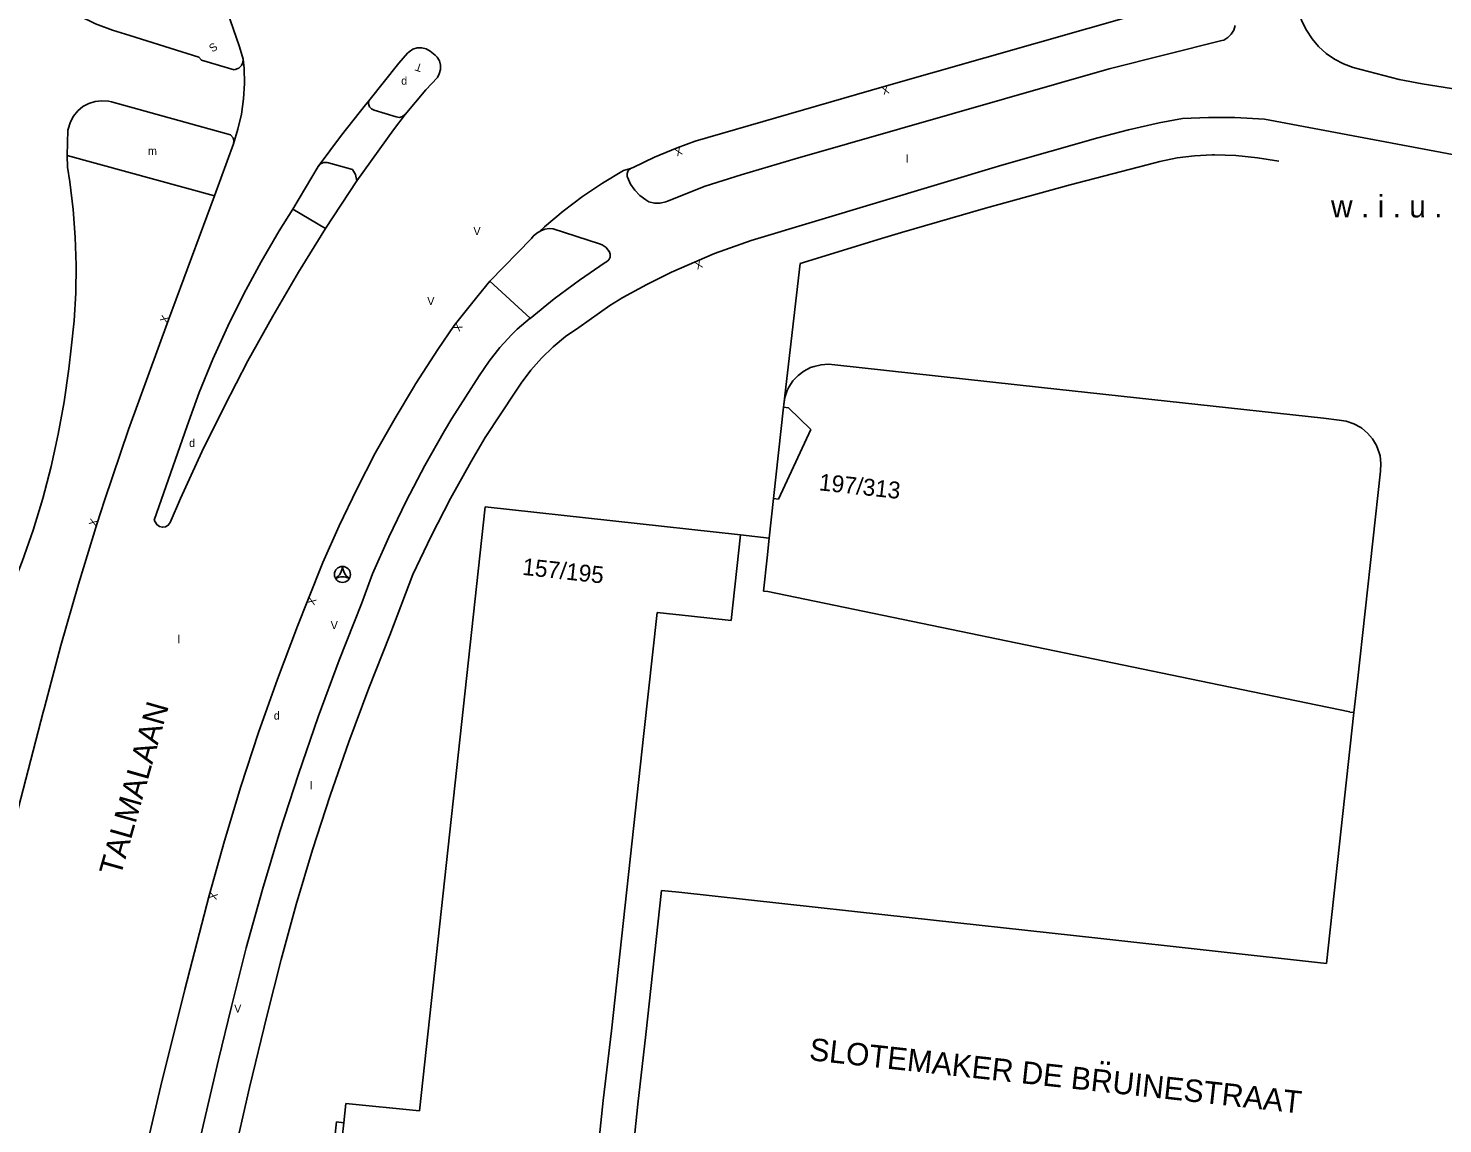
# Model space of a CAD drawing. Extents: x 134999 to 136502, y 457398 to 459002.
# Drawn here: x 136333.3 to 136421.7, y 457501.4 to 457569.8 of the extents above; entities that cross this region are included whole.
import ezdxf

# ---------------------------------------------------------------- set-up
doc = ezdxf.new("R2010")
doc.units = 0
for name, color, linetype in [('RI_DGTB_2', 7, 'Continuous'), ('RI_DGTB_29', 7, 'Continuous'), ('RI_DGTB_30', 7, 'Continuous'), ('RI_DGTB_31', 7, 'Continuous'), ('RI_DGTB_35', 7, 'Continuous'), ('RI_DGTB_37', 7, 'Continuous'), ('RI_DGTB_41', 7, 'Continuous'), ('RI_DGTB_43', 7, 'Continuous'), ('RI_DGTB_53', 7, 'Continuous')]:
    doc.layers.add(name, color=color, linetype=linetype)

msp = doc.modelspace()

# ---------------------------------------------------------------- linework, layer by layer
at = {"layer": 'RI_DGTB_2'}
for p, q in [((136383.707, 457548.805), (136396.602, 457547.404)), ((136396.602, 457547.404), (136414.227, 457545.473)), ((136380.802, 457546.12), (136380.484, 457546.155)), ((136380.802, 457546.12), (136382.208, 457544.769)), ((136382.208, 457544.769), (136380.185, 457540.413)), ((136415.208, 457545.362), (136414.227, 457545.473)), ((136416.337, 457529.049), (136417.785, 457542.17)), ((136380.185, 457540.413), (136379.867, 457540.448)), ((136357.748, 457502.191), (136361.858, 457539.928)), ((136361.858, 457539.928), (136377.797, 457538.177)), ((136377.797, 457538.177), (136377.215, 457532.834)), ((136377.797, 457538.177), (136379.6, 457537.982)), ((136379.238, 457534.668), (136379.467, 457536.757)), ((136379.238, 457534.668), (136379.519, 457534.648)), ((136406.472, 457529.066), (136379.519, 457534.648)), ((136406.472, 457529.066), (136415.875, 457527.123)), ((136416.337, 457529.049), (136416.12, 457527.078)), ((136416.12, 457527.078), (136414.41, 457511.403)), ((136415.873, 457527.098), (136415.875, 457527.123)), ((136416.12, 457527.078), (136415.873, 457527.098)), ((136372.873, 457515.963), (136371.882, 457506.957)), ((136372.873, 457515.963), (136373.958, 457515.852)), ((136373.958, 457515.852), (136386.818, 457514.44)), ((136386.818, 457514.44), (136400.116, 457512.982)), ((136400.116, 457512.982), (136414.41, 457511.403)), ((136369.743, 457507.19), (136369.234, 457502.841)), ((136371.882, 457506.957), (136371.396, 457502.605)), ((136353.154, 457502.648), (136357.748, 457502.191)), ((136369.234, 457502.841), (136368.971, 457500.431)), ((136371.396, 457502.605), (136371.133, 457500.195)), ((136352.264, 457498.731), (136352.569, 457501.494))]:
    msp.add_line(p, q, dxfattribs=at)
for points in [[(136380.823, 457547.412), (136381.079, 457547.801), (136381.398, 457548.142), (136381.771, 457548.423), (136382.186, 457548.636), (136382.397, 457548.713)], [(136382.397, 457548.713), (136382.843, 457548.82), (136383.3, 457548.848), (136383.707, 457548.805)], [(136380.503, 457546.331), (136380.57, 457546.774), (136380.715, 457547.198), (136380.823, 457547.412)], [(136379.867, 457540.448), (136380.484, 457546.155)], [(136380.484, 457546.155), (136380.503, 457546.331)], [(136416.547, 457544.899), (136416.11, 457545.129), (136415.642, 457545.287), (136415.208, 457545.362)], [(136417.707, 457543.318), (136417.534, 457543.765), (136417.289, 457544.177), (136416.979, 457544.543), (136416.613, 457544.853), (136416.547, 457544.899)], [(136417.785, 457542.17), (136417.809, 457542.648), (136417.753, 457543.123), (136417.707, 457543.318)], [(136379.6, 457537.982), (136379.867, 457540.448)], [(136379.467, 457536.757), (136379.6, 457537.982)], [(136372.591, 457533.331), (136371.768, 457525.777)], [(136374.74, 457533.1), (136372.591, 457533.331)], [(136377.215, 457532.834), (136374.74, 457533.1)], [(136371.768, 457525.777), (136369.743, 457507.19)], [(136353.154, 457502.648), (136353.02, 457501.444)], [(136352.569, 457501.494), (136353.02, 457501.444)], [(136353.02, 457501.444), (136352.712, 457498.682)]]:
    msp.add_lwpolyline(points, dxfattribs=at)
at = {"layer": 'RI_DGTB_31'}
msp.add_circle((136352.941, 457535.713), 0.5, dxfattribs=at)
for centre, radius, start, end in [((136351.959, 457536.281), 0.984, 303.89611, 356.03804), ((136353.921, 457536.28), 0.982, 183.93068, 236.24524), ((136352.941, 457534.564), 0.999, 64.2764, 115.72044)]:
    msp.add_arc(centre, radius, start, end, dxfattribs=at)
at = {"layer": 'RI_DGTB_53'}
for p, q in [((136346.176, 457567.241), (136344.128, 457567.847)), ((136358.739, 457568.158), (136358.412, 457568.405)), ((136418.951, 457566.64), (136416.07, 457567.389)), ((136338.519, 457565.242), (136345.951, 457563.175)), ((136354.926, 457564.722), (136356.306, 457564.301)), ((136335.736, 457561.886), (136344.944, 457559.364)), ((136352.063, 457561.444), (136353.577, 457561.009)), ((136349.841, 457558.531), (136351.426, 457561.215)), ((136370.49, 457560.95), (136370.931, 457561.085)), ((136353.838, 457560.312), (136351.883, 457557.325)), ((136373.25, 457559.035), (136375.598, 457559.983)), ((136349.841, 457558.531), (136351.883, 457557.325)), ((136368.989, 457556.383), (136366.112, 457557.3)), ((136378.462, 457556.59), (136376.191, 457555.776)), ((136376.191, 457555.776), (136375.07, 457555.29)), ((136362.149, 457554.038), (136361.959, 457553.803)), ((136364.658, 457551.717), (136362.149, 457554.038)), ((136363.854, 457551.034), (136364.658, 457551.717)), ((136369.64, 457552.524), (136367.703, 457551.153)), ((136341.187, 457539.112), (136343.234, 457545.007)), ((136354.825, 457535.757), (136354.121, 457533.874)), ((136357.337, 457535.707), (136355.906, 457531.912))]:
    msp.add_line(p, q, dxfattribs=at)
for points in [[(136342.899, 457576.881), (136343.766, 457575.308), (136344.562, 457573.699), (136345.286, 457572.055), (136345.936, 457570.381), (136346.51, 457568.68), (136346.74, 457567.921)], [(136373.85, 457562.374), (136374.967, 457562.791), (136386.769, 457566.213), (136402.637, 457570.732), (136407.626, 457572.206)], [(136339.667, 457569.387), (136338.581, 457569.721), (136337.521, 457570.131), (136336.493, 457570.615), (136335.502, 457571.169), (136334.563, 457571.784)], [(136416.07, 457567.389), (136415.474, 457567.613), (136414.912, 457567.909), (136414.391, 457568.274), (136413.92, 457568.702), (136413.506, 457569.185), (136413.156, 457569.716), (136412.875, 457570.287), (136412.668, 457570.889), (136412.538, 457571.512), (136412.527, 457571.599)], [(136344.128, 457567.847), (136343.98, 457568.035), (136339.667, 457569.387)], [(136408.695, 457570.018), (136408.617, 457569.727), (136408.465, 457569.468), (136408.251, 457569.258), (136407.989, 457569.111), (136407.878, 457569.074)], [(136358.412, 457568.405), (136358.168, 457568.552), (136357.893, 457568.626), (136357.609, 457568.621), (136357.337, 457568.538), (136357.098, 457568.382), (136357.007, 457568.292)], [(136407.878, 457569.074), (136400.835, 457567.307), (136381.22, 457561.683)], [(136346.126, 457562.628), (136346.416, 457563.542), (136346.63, 457564.477), (136346.764, 457565.426), (136346.819, 457566.383), (136346.794, 457567.342), (136346.74, 457567.921)], [(136346.74, 457567.921), (136346.722, 457567.705), (136346.628, 457567.509), (136346.471, 457567.361), (136346.176, 457567.241)], [(136357.008, 457568.293), (136356.46, 457567.656), (136354.597, 457565.316)], [(136358.983, 457566.993), (136359.067, 457567.259), (136359.073, 457567.537), (136358.999, 457567.805), (136358.853, 457568.042), (136358.738, 457568.158)], [(136356.854, 457564.464), (136358.149, 457566.002), (136358.884, 457566.759), (136358.984, 457566.994)], [(136430.208, 457565.017), (136426.927, 457565.391), (136423.649, 457565.846), (136420.384, 457566.38), (136418.951, 457566.64)], [(136335.78, 457563.47), (136335.946, 457563.995), (136336.146, 457564.361), (136336.412, 457564.682), (136336.734, 457564.947), (136337.1, 457565.145), (136337.498, 457565.27), (136337.912, 457565.317), (136338.328, 457565.285), (136338.519, 457565.242)], [(136351.426, 457561.215), (136352.876, 457563.165), (136354.39, 457565.066), (136354.597, 457565.316)], [(136354.596, 457565.316), (136354.575, 457565.126), (136354.632, 457564.943), (136354.758, 457564.8), (136354.926, 457564.721)], [(136353.838, 457560.312), (136356.139, 457563.501), (136356.854, 457564.464)], [(136356.306, 457564.3), (136356.501, 457564.274), (136356.69, 457564.327), (136356.843, 457564.451), (136356.854, 457564.464)], [(136400.134, 457562.998), (136402.032, 457563.504), (136403.963, 457563.937), (136405.419, 457564.209)], [(136405.419, 457564.209), (136407.048, 457564.277), (136408.679, 457564.264), (136410.541, 457564.158)], [(136410.541, 457564.158), (136429.479, 457560.599), (136433.194, 457559.97)], [(136335.736, 457561.886), (136335.78, 457563.47)], [(136346.126, 457562.628), (136344.944, 457559.364)], [(136345.951, 457563.175), (136346.107, 457562.99), (136346.156, 457562.811), (136346.126, 457562.628)], [(136373.85, 457562.374), (136372.433, 457561.784), (136371.11, 457561.152)], [(136378.462, 457556.59), (136394.132, 457561.287), (136400.134, 457562.998)], [(136335.756, 457561.168), (136335.736, 457561.886)], [(136351.426, 457561.215), (136351.575, 457561.366), (136351.77, 457561.452), (136351.982, 457561.461), (136352.063, 457561.444)], [(136381.22, 457561.683), (136377.837, 457560.693), (136375.598, 457559.983)], [(136403.687, 457561.442), (136398.391, 457560.065), (136393.115, 457558.612), (136387.862, 457557.081), (136386.622, 457556.708)], [(136407.259, 457561.94), (136406.165, 457561.88), (136405.079, 457561.741), (136404.006, 457561.523), (136403.687, 457561.442)], [(136411.428, 457561.544), (136410.096, 457561.755), (136408.754, 457561.887), (136407.406, 457561.939), (136407.259, 457561.94)], [(136335.987, 457549.843), (136336.173, 457551.571), (136336.279, 457553.305), (136336.305, 457555.043), (136336.251, 457556.78), (136336.118, 457558.513), (136335.904, 457560.238), (136335.756, 457561.168)], [(136353.577, 457561.009), (136353.764, 457560.698), (136353.838, 457560.312)], [(136370.49, 457560.95), (136369.191, 457560.172), (136367.934, 457559.326), (136366.724, 457558.415), (136365.564, 457557.442), (136365.219, 457557.132)], [(136371.11, 457561.152), (136370.931, 457561.085), (136370.795, 457560.951), (136370.725, 457560.774), (136370.733, 457560.583), (136370.749, 457560.533)], [(136370.749, 457560.533), (136370.939, 457560.109), (136371.199, 457559.723), (136371.521, 457559.388), (136371.896, 457559.113), (136372.089, 457559.006)], [(136344.944, 457559.364), (136342.073, 457551.614), (136339.572, 457544.779)], [(136372.089, 457559.006), (136372.438, 457558.924), (136372.797, 457558.92), (136373.148, 457558.997), (136373.25, 457559.035)], [(136343.234, 457545.007), (136343.998, 457547.079), (136344.853, 457549.169), (136345.782, 457551.227), (136346.783, 457553.251), (136347.856, 457555.239), (136348.998, 457557.187), (136349.841, 457558.531)], [(136351.883, 457557.325), (136350.199, 457554.612), (136348.585, 457551.858), (136347.04, 457549.065), (136345.565, 457546.234), (136344.162, 457543.367), (136342.831, 457540.465), (136342.171, 457538.951)], [(136365.34, 457557.182), (136365.076, 457557.047), (136364.858, 457556.847), (136364.753, 457556.696)], [(136366.112, 457557.3), (136365.844, 457557.338), (136365.577, 457557.296), (136365.34, 457557.182)], [(136364.753, 457556.696), (136362.148, 457554.038)], [(136369.588, 457555.924), (136369.406, 457556.147), (136369.171, 457556.311), (136368.989, 457556.383)], [(136386.623, 457556.708), (136381.535, 457555.141), (136380.503, 457546.331)], [(136369.427, 457555.248), (136369.574, 457555.373), (136369.657, 457555.545), (136369.664, 457555.737), (136369.593, 457555.915), (136369.588, 457555.924)], [(136375.069, 457555.289), (136373.494, 457554.601), (136371.952, 457553.841), (136370.448, 457553.009), (136369.639, 457552.524)], [(136364.657, 457551.716), (136366.173, 457552.941), (136367.738, 457554.102), (136369.35, 457555.198), (136369.427, 457555.248)], [(136359.921, 457551.269), (136361.333, 457553.033), (136362.149, 457554.038)], [(136357.373, 457547.392), (136357.528, 457547.65), (136358.897, 457549.773), (136359.921, 457551.269)], [(136361.476, 457548.124), (136362.096, 457549.035), (136362.78, 457549.898), (136363.524, 457550.71), (136363.854, 457551.033)], [(136367.703, 457551.152), (136366.875, 457550.573), (136366.097, 457549.931), (136365.371, 457549.229), (136364.703, 457548.472), (136364.097, 457547.664), (136363.765, 457547.157)], [(136331.358, 457532.688), (136332.189, 457534.593), (136332.941, 457536.519), (136333.618, 457538.473), (136334.219, 457540.451), (136334.743, 457542.451), (136335.189, 457544.471), (136335.557, 457546.505), (136335.846, 457548.553), (136335.987, 457549.843)], [(136350.781, 457534.104), (136351.724, 457536.447), (136352.742, 457538.759), (136353.832, 457541.038), (136354.994, 457543.281), (136356.226, 457545.486), (136357.373, 457547.392)], [(136361.476, 457548.124), (136359.771, 457545.461)], [(136361.856, 457544.269), (136363.765, 457547.157)], [(136339.572, 457544.779), (136338.084, 457540.325), (136337.629, 457538.909)], [(136354.825, 457535.757), (136355.84, 457538.043), (136356.927, 457540.296), (136358.086, 457542.513), (136359.315, 457544.692), (136359.771, 457545.461)], [(136357.337, 457535.707), (136358.477, 457538.095), (136359.689, 457540.448), (136360.971, 457542.763), (136361.855, 457544.269)], [(136337.629, 457538.909), (136336.449, 457535.096), (136335.347, 457531.261), (136334.322, 457527.404), (136334.246, 457527.108)], [(136342.171, 457538.951), (136342.058, 457538.79), (136341.89, 457538.686), (136341.695, 457538.656), (136341.504, 457538.705), (136341.347, 457538.826), (136341.187, 457539.112)], [(136344.624, 457515.653), (136345.574, 457519.068), (136346.601, 457522.461), (136347.705, 457525.829), (136348.884, 457529.172), (136350.138, 457532.487), (136350.781, 457534.104)], [(136346.003, 457508.704), (136346.933, 457512.369), (136347.941, 457516.014), (136349.025, 457519.637), (136350.186, 457523.235), (136351.422, 457526.809), (136352.734, 457530.356), (136354.121, 457533.874)], [(136348.248, 457508.183), (136349.113, 457511.642), (136350.055, 457515.081), (136351.073, 457518.498), (136352.168, 457521.891), (136353.339, 457525.259), (136354.585, 457528.6), (136355.906, 457531.912)], [(136334.246, 457527.108), (136332.548, 457520.509), (136332.22, 457519.27)], [(136340.187, 457497.703), (136341.598, 457503.741), (136343.087, 457509.761), (136344.624, 457515.653)], [(136341.332, 457486.425), (136342.175, 457491.165), (136343.101, 457495.916), (136344.105, 457500.651), (136345.188, 457505.368), (136346.003, 457508.704)], [(136343.364, 457484.908), (136344.189, 457489.615), (136345.093, 457494.308), (136346.076, 457498.986), (136347.136, 457503.646), (136348.248, 457508.183)]]:
    msp.add_lwpolyline(points, dxfattribs=at)

# ---------------------------------------------------------------- texts
at = {"layer": 'RI_DGTB_29'}
msp.add_text('S', height=0.5, rotation=34.85991, dxfattribs=at).set_placement((136344.826, 457568.318))
for p in [(136356.614, 457566.318), (136343.364, 457543.68), (136348.654, 457526.64)]:
    msp.add_text('d', height=0.5, dxfattribs=at).set_placement(p)
at = {"layer": 'RI_DGTB_30'}
for rotation, p in [(196.16983, (136387.009, 457566.283)), (202.03338, (136374.048, 457562.455)), (203.4585, (136375.299, 457555.39)), (69.67176, (136341.986, 457551.38)), (238.31629, (136360.052, 457551.482)), (72.03222, (136337.552, 457538.672)), (249.58092, (136350.868, 457534.338)), (255.60319, (136344.687, 457515.895))]:
    msp.add_text('X', height=0.5, rotation=rotation, dxfattribs=at).set_placement(p)
for p in [(136361.123, 457556.917), (136358.24, 457552.545), (136352.205, 457532.292), (136346.179, 457508.331)]:
    msp.add_text('V', height=0.5, dxfattribs=at).set_placement(p)
at = {"layer": 'RI_DGTB_31'}
msp.add_text('T', height=0.5, rotation=161.67425, dxfattribs=at).set_placement((136357.98, 457567.571))
at = {"layer": 'RI_DGTB_35'}
for s, p in [('197/313', (136382.67, 457540.975)), ('157/195', (136364.142, 457535.69))]:
    msp.add_text(s, height=1.054, rotation=353.8023, dxfattribs=at).set_placement(p)
at = {"layer": 'RI_DGTB_37'}
for s, rotation, p in [('TALMALAAN', 74.20264, (136339.075, 457516.793)), ('SLOTEMAKER DE BRUINESTRAAT', 353.7896, (136382.055, 457505.36)), ('.', 353.74577, (136400.128, 457505.121)), ('.', 353.74577, (136400.519, 457505.081))]:
    msp.add_text(s, height=1.4, rotation=rotation, dxfattribs=at).set_placement(p)
at = {"layer": 'RI_DGTB_41'}
msp.add_text('w . i . u .', height=1.4, dxfattribs=at).set_placement((136414.689, 457558.023))
at = {"layer": 'RI_DGTB_43'}
for s, p in [('m', (136340.792, 457561.933)), ('l', (136388.136, 457561.446)), ('l', (136342.653, 457531.411)), ('l', (136350.909, 457522.283))]:
    msp.add_text(s, height=0.5, dxfattribs=at).set_placement(p)

doc.saveas('drawing.dxf')
